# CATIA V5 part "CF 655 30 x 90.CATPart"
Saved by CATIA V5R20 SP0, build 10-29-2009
Part number: CF 655 30 x 90
Definition: NONE
Nomenclature: CF 655 30 x 90
Source: Unknown
Description: CF 655 30 x 90
Bounding box of the stored display mesh (mm): x -64 to 26, y -26.5 to 26.5, z -26.5 to 26.5
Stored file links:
  C:\Users\Utente\Desktop\IO LAVORO\3D X SITO CF\X SITO\CF 655\CF 655 30 x 90.CATPart
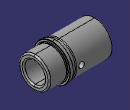
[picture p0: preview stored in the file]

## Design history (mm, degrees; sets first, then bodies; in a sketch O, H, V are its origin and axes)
Body1 "CF 655 30 x 90" (main body)
  Solid1: solid without history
